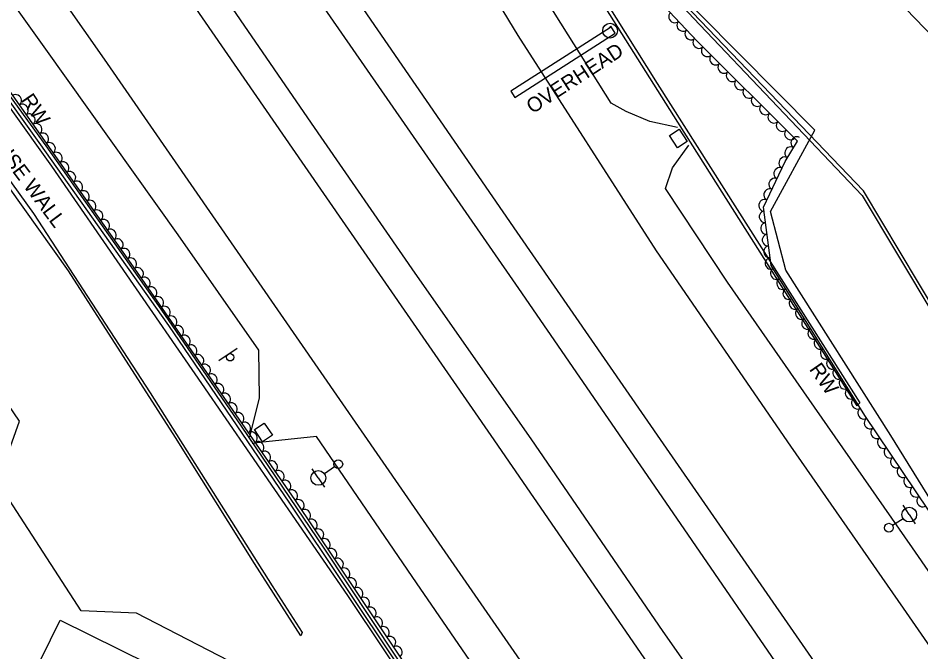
# Model space of a CAD drawing. Extents: x 1722896 to 1754269, y 648279 to 666297.
# Drawn here: x 1731749.4 to 1732056.4, y 650839.6 to 651055.3 of the extents above; entities that cross this region are included whole.
import ezdxf

# ---------------------------------------------------------------- set-up
doc = ezdxf.new("R2010")
doc.units = 0
for name, color, linetype in [('DESIGN - CENTERLINE - Proposed Text', 7, 'Continuous'), ('DESIGN - PUBLIC HEARING - Shapes', 7, 'Continuous'), ('DESIGN - SCRATCH - User 1', 7, 'Continuous'), ('SURVEY - CENTERLINE - Preliminary', 7, 'Continuous'), ('SURVEY - CENTERLINE - Preliminary Text', 7, 'Continuous'), ('SURVEY - DRAINAGE - Natural Features', 7, 'Continuous'), ('SURVEY - DTM - Breaklines', 7, 'Continuous'), ('SURVEY - VEGETATION - Features with Text', 7, 'Continuous')]:
    doc.layers.add(name, color=color, linetype=linetype)

msp = doc.modelspace()

# ---------------------------------------------------------------- linework, layer by layer
at = {"layer": 'DESIGN - CENTERLINE - Proposed Text'}
msp.add_lwpolyline([(1731780.41, 650808.63), (1731750.38, 650823.44), (1731763.68, 650850.4), (1731793.71, 650835.59)], close=True, dxfattribs=at)
at = {"layer": 'DESIGN - PUBLIC HEARING - Shapes'}
for p, q in [((1731950.78, 651052.04), (1731916.88, 651030.45)), ((1731950.91, 651052.54), (1731950.38, 651051.91)), ((1731952.44, 651050.16), (1731950.91, 651052.54)), ((1731918.25, 651028.26), (1731952.44, 651050.16)), ((1731950.68, 651050.98), (1731950.68, 651050.98)), ((1731916.88, 651030.45), (1731918.25, 651028.26)), ((1731817.67, 650938.77), (1731823.88, 650942.97))]:
    msp.add_line(p, q, dxfattribs=at)
for centre, radius in [((1731950.68, 651051), 2.5), ((1731821.48, 650939.87), 1.25)]:
    msp.add_circle(centre, radius, dxfattribs=at)
at = {"layer": 'DESIGN - SCRATCH - User 1'}
for points in [[(1731680.63, 651501.51), (1731706.68, 651458.5), (1731762.77, 651364.89), (1731797.2, 651307.65), (1731864.33, 651196.37), (1731896.93, 651142.43), (1731941.96, 651095.08), (1731979.08, 651055.22), (1732036.37, 650994.91), (1732060.81, 650954.19), (1732114.18, 650865.36), (1732129.08, 650840.67), (1732130.55, 650841.67), (1732086.72, 650912.98), (1732036.79, 650996.49), (1731973.45, 651062.76), (1731898, 651143.62), (1731862.11, 651202.73), (1731801.43, 651303.37), (1731762.87, 651367.01), (1731706.71, 651460.76), (1731681.59, 651502.39), (1731680.63, 651501.51)], [(1731845.46, 650845.06), (1731829.79, 650869.74), (1731802.93, 650912.6), (1731766.54, 650969.25), (1731721.31, 651032.63), (1731670.36, 651104.51), (1731614.93, 651181.38), (1731578.56, 651233.28), (1731531.39, 651304.53), (1731532.39, 651305.05), (1731571.46, 651245.99), (1731615.93, 651181.71), (1731665.93, 651112.54), (1731712.43, 651047.28), (1731754.65, 650988.78), (1731794.25, 650927.74), (1731835.8, 650862.08), (1731846.02, 650846.2), (1731845.46, 650845.06)], [(1732034.69, 650923.36), (1732003.06, 650973.48), (1731972.32, 651022.07), (1731941.05, 651071.73), (1731904.54, 651126.39), (1731894.7, 651142.29), (1731894.86, 651142.36)], [(1731895.88, 651142.78), (1731895.94, 651142.8), (1731906.58, 651125.2), (1731941.84, 651072.73), (1731966.69, 651032.99), (1731998.4, 650983.02), (1732035.61, 650924.43), (1732034.69, 650923.36)], [(1731711.45, 651075.97), (1731756.46, 651012.92), (1731800.47, 650950.64), (1731841.61, 650890.2), (1731878.83, 650834.58), (1731941.61, 650740.85), (1731974.68, 650690.75), (1731975.76, 650691.44), (1731953.79, 650724.47), (1731919.13, 650776.17), (1731885.86, 650826.09), (1731853.46, 650874.88), (1731825.32, 650916.45), (1731798.06, 650956.2), (1731758.89, 651011.87), (1731723.91, 651060.09)]]:
    msp.add_lwpolyline(points, dxfattribs=at)
at = {"layer": 'SURVEY - CENTERLINE - Preliminary'}
for points in [[(1731987.56, 651124.54), (1732076.69, 651031.96), (1732139.09, 650944.54), (1732141.6, 650942.26)], [(1732086.13, 650848.59), (1732046.09, 650913.21), (1732010.44, 650969.5), (1732005.18, 650989.51), (1732020.29, 651017.12), (1731968.54, 651069.55)], [(1731719.74, 651062.41), (1731760.69, 651004.94), (1731811.77, 650930.95), (1731861.34, 650858.86), (1731911.05, 650784.52), (1731953.32, 650720.36), (1731972.7, 650690.52), (1731957.5, 650673.39), (1731935.16, 650693.97), (1731925.57, 650696.42), (1731909.01, 650693.57), (1731912.5, 650678.75), (1731923.45, 650652.45), (1731950.19, 650614.84)], [(1731941.83, 650605.02), (1731903.93, 650655.14), (1731868.65, 650709.61), (1731883.74, 650722.54), (1731896.34, 650740.19), (1731872.01, 650780.24), (1731857.08, 650775.11), (1731841.22, 650782.51), (1731846.88, 650797.67), (1731841.95, 650819.95), (1731828.03, 650832.91), (1731789.69, 650852.77), (1731770.8, 650853.6), (1731742.33, 650897.36), (1731749.84, 650918.11), (1731736.25, 650937.95)]]:
    msp.add_lwpolyline(points, dxfattribs=at)
at = {"layer": 'SURVEY - CENTERLINE - Preliminary Text'}
for points in [[(1731973.59, 651018.03), (1731964.22, 651020.08), (1731956.1, 651023.54), (1731951.02, 651026.37), (1731931.96, 651056.63), (1731892.47, 651121.33), (1731857.59, 651177.14), (1731825.98, 651228.44), (1731803.59, 651264.54), (1731802.08, 651263.28), (1731780.81, 651294.54), (1731758.29, 651329.07), (1731711.05, 651401.41), (1731683.3, 651444.9), (1731661.53, 651480.68)], [(1732085.65, 650803.56), (1732050.4, 650854.57), (1732012.17, 650909.59), (1731966.42, 650976.11), (1731919.38, 651049.41), (1731882.1, 651110.79), (1731849.88, 651162.67), (1731820.44, 651210.26), (1731770.77, 651290.85), (1731726.03, 651363.67), (1731682.44, 651434.5), (1731656.79, 651476.05)], [(1731616.26, 651421.62), (1731673.55, 651338.68), (1731726.54, 651261.54), (1731771.3, 651196.63), (1731821.79, 651123.39), (1731866.78, 651058.16), (1731918.97, 650982.49), (1731968.69, 650910.45), (1732015.97, 650842.13), (1732059.47, 650779.19)], [(1731609.29, 651412.47), (1731640.1, 651367.94), (1731672.44, 651320.08), (1731705.09, 651273.95), (1731739.88, 651223.41), (1731771.76, 651177.96), (1731804.85, 651129.23), (1731841.88, 651075.46), (1731880.61, 651019.43), (1731919.55, 650963.26), (1731970.71, 650888.77), (1732015.82, 650823.2), (1732046.06, 650780.13), (1732051.86, 650771.78)], [(1732032.9, 650754.58), (1732001.01, 650800.45), (1731968.72, 650846.62), (1731923.79, 650912.09), (1731884.37, 650968.55), (1731849.18, 651019.58), (1731812.26, 651073.26), (1731756.99, 651153.56), (1731679.87, 651265.16), (1731634.52, 651331.21), (1731592.81, 651391.29)], [(1732025.14, 650747.43), (1731976.82, 650816.5), (1731910.23, 650913.3), (1731847.03, 651004.74), (1731792.34, 651084.02), (1731736.24, 651165.32), (1731675.77, 651253.11), (1731613.26, 651343.4), (1731586.88, 651382.19)], [(1731558.13, 651341.59), (1731611.18, 651270.98), (1731669.4, 651193.37), (1731730.92, 651109.38), (1731778.62, 651041.25), (1731831.25, 650965.22), (1731893.44, 650875.12), (1731953.62, 650788.12), (1731998.3, 650723.5)], [(1731828.16, 650912.84), (1731831.44, 650926.12), (1731831.28, 650942.25), (1731803.84, 650981.51), (1731758.79, 651044.68), (1731711.49, 651110.83), (1731670.01, 651168.59), (1731629.92, 651224.18), (1731584.4, 651287.39), (1731550.85, 651332.66)], [(1732095.97, 650813.6), (1732086.47, 650827.35), (1732053.52, 650875.04), (1732020.23, 650922.85), (1731990.63, 650965.39), (1731969.53, 650997.26), (1731971.88, 651004.35), (1731977.41, 651012.05)], [(1731988.06, 650713.96), (1731958.33, 650756.26), (1731921.08, 650810.29), (1731884.84, 650863.16), (1731850.81, 650912.9), (1731831.53, 650910.92), (1731828.99, 650910.56)]]:
    msp.add_lwpolyline(points, dxfattribs=at)
at = {"layer": 'SURVEY - DRAINAGE - Natural Features'}
for p, q in [((1731973.9, 651014.3), (1731973.9, 651014.3)), ((1731832.8, 650914.3), (1731832.8, 650914.3))]:
    msp.add_line(p, q, dxfattribs=at)
for points in [[(1731970.86, 651015.3), (1731974.2, 651017.49), (1731976.94, 651013.31), (1731973.6, 651011.12), (1731970.86, 651015.3)], [(1731829.75, 650915.28), (1731833.08, 650917.49), (1731835.85, 650913.32), (1731832.52, 650911.11), (1731829.75, 650915.28)]]:
    msp.add_lwpolyline(points, dxfattribs=at)
at = {"layer": 'SURVEY - DTM - Breaklines'}
for p, q in [((1731851.46, 650898.81), (1731849.32, 650901.89)), ((1731857.01, 650902.65), (1731853.52, 650900.23)), ((1731851.46, 650898.81), (1731853.6, 650895.73)), ((1732052.42, 650886.36), (1732050.39, 650889.51)), ((1732052.42, 650886.36), (1732054.46, 650883.2)), ((1732046.75, 650882.7), (1732050.32, 650885))]:
    msp.add_line(p, q, dxfattribs=at)
for centre, radius in [((1731858.24, 650903.51), 1.5), ((1731851.46, 650898.81), 2.5), ((1732052.42, 650886.36), 2.5), ((1732045.49, 650881.88), 1.5)]:
    msp.add_circle(centre, radius, dxfattribs=at)
at = {"layer": 'SURVEY - VEGETATION - Features with Text'}
for points in [[(1731530.89, 651319.05), (1731544.8, 651312.52), (1731576.63, 651263.74), (1731630.16, 651191.72), (1731685.22, 651113.78), (1731734.6, 651047.2), (1731791.48, 650966.44), (1731843.4, 650891.46), (1731899.83, 650807.18), (1731951.2, 650728.8), (1731974.6, 650694.21), (1731967.75, 650683.16), (1731959.89, 650675.49), (1731953.96, 650673.37), (1731949.61, 650676.7), (1731938.65, 650685.2), (1731929.31, 650693.1), (1731920.84, 650695.65), (1731912.41, 650691.48), (1731911.03, 650689.1), (1731921.95, 650666.12), (1731927.9, 650651.9), (1731954.2, 650614.68), (1731943.01, 650602.57)], [(1732236.41, 650804.23), (1732221.96, 650790.42), (1732206.79, 650789.89), (1732190.78, 650792.42), (1732172.9, 650795.01), (1732158.48, 650800.33), (1732149.18, 650802.17), (1732140.53, 650808.37), (1732131.57, 650816.91), (1732127.28, 650828.29), (1732118.85, 650825.83), (1732111.88, 650818.36), (1732106.8, 650818.16), (1732100, 650825.57), (1732085.7, 650844.61), (1732063.41, 650881.31), (1732037.28, 650920.08), (1732005.41, 650971.08), (1732002.86, 650990.97), (1732010.17, 651006.46), (1732014.37, 651013.43), (1731980.28, 651047.46), (1731938.47, 651091.92)]]:
    msp.add_lwpolyline(points, dxfattribs=at)
for centre, major_axis in [((1731972.58, 651055.65), (-1.37, 1.46)), ((1731975.32, 651052.74), (-1.37, 1.46)), ((1731978.06, 651049.82), (-1.37, 1.46)), ((1731980.81, 651046.93), (-1.42, 1.41)), ((1731983.65, 651044.1), (-1.42, 1.41)), ((1731986.48, 651041.28), (-1.42, 1.41)), ((1731989.31, 651038.45), (-1.42, 1.41)), ((1731992.14, 651035.62), (-1.42, 1.41)), ((1731994.97, 651032.8), (-1.42, 1.41)), ((1731997.8, 651029.97), (-1.42, 1.41)), ((1731748.61, 651027.3), (1.15, -1.64)), ((1732000.63, 651027.15), (-1.42, 1.41)), ((1731750.91, 651024.03), (1.15, -1.64)), ((1732003.46, 651024.32), (-1.42, 1.41)), ((1731753.22, 651020.76), (1.15, -1.64)), ((1732006.29, 651021.5), (-1.42, 1.41)), ((1731755.52, 651017.49), (1.15, -1.64)), ((1732009.13, 651018.67), (-1.42, 1.41)), ((1731757.82, 651014.22), (1.15, -1.64)), ((1732011.96, 651015.84), (-1.42, 1.41)), ((1732014.07, 651012.93), (1.03, 1.71)), ((1731760.13, 651010.95), (1.15, -1.64)), ((1731762.43, 651007.68), (1.15, -1.64)), ((1732012, 651009.51), (1.03, 1.71)), ((1731764.73, 651004.41), (1.15, -1.64)), ((1732009.98, 651006.06), (0.85, 1.81)), ((1731767.04, 651001.14), (1.15, -1.64)), ((1732008.27, 651002.44), (0.85, 1.81)), ((1731769.34, 650997.87), (1.15, -1.64)), ((1732006.56, 650998.82), (0.85, 1.81)), ((1731771.64, 650994.6), (1.15, -1.64)), ((1732004.86, 650995.21), (0.85, 1.81)), ((1731773.95, 650991.33), (1.15, -1.64)), ((1732003.15, 650991.59), (0.85, 1.81)), ((1731776.25, 650988.06), (1.15, -1.64)), ((1732003.28, 650987.68), (-0.25, 1.98)), ((1731778.55, 650984.79), (1.15, -1.64)), ((1732003.79, 650983.71), (-0.25, 1.98)), ((1731780.86, 650981.52), (1.15, -1.64)), ((1732004.3, 650979.75), (-0.25, 1.98)), ((1731783.16, 650978.25), (1.15, -1.64)), ((1731785.46, 650974.98), (1.15, -1.64)), ((1732004.8, 650975.78), (-0.25, 1.98)), ((1731787.77, 650971.71), (1.15, -1.64)), ((1732005.31, 650971.81), (-0.25, 1.98)), ((1731790.07, 650968.43), (1.15, -1.64)), ((1732007.14, 650968.31), (-1.06, 1.7)), ((1731792.36, 650965.16), (1.14, -1.64)), ((1732009.26, 650964.92), (-1.06, 1.7)), ((1731794.64, 650961.87), (1.14, -1.64)), ((1732011.38, 650961.53), (-1.06, 1.7)), ((1731796.92, 650958.58), (1.14, -1.64)), ((1732013.5, 650958.14), (-1.06, 1.7)), ((1731799.19, 650955.29), (1.14, -1.64)), ((1731801.47, 650952), (1.14, -1.64)), ((1732015.62, 650954.75), (-1.06, 1.7)), ((1731803.75, 650948.72), (1.14, -1.64)), ((1732017.74, 650951.35), (-1.06, 1.7)), ((1731806.03, 650945.43), (1.14, -1.64)), ((1732019.86, 650947.96), (-1.06, 1.7)), ((1731808.3, 650942.14), (1.14, -1.64)), ((1732021.98, 650944.57), (-1.06, 1.7)), ((1732024.1, 650941.18), (-1.06, 1.7)), ((1731810.58, 650938.85), (1.14, -1.64)), ((1732026.22, 650937.79), (-1.06, 1.7)), ((1731812.86, 650935.56), (1.14, -1.64)), ((1732028.34, 650934.39), (-1.06, 1.7)), ((1731815.14, 650932.27), (1.14, -1.64)), ((1732030.46, 650931), (-1.06, 1.7)), ((1731817.41, 650928.98), (1.14, -1.64)), ((1732032.58, 650927.61), (-1.06, 1.7)), ((1731819.69, 650925.7), (1.14, -1.64)), ((1732034.7, 650924.22), (-1.06, 1.7)), ((1731821.97, 650922.41), (1.14, -1.64)), ((1731824.24, 650919.12), (1.14, -1.64)), ((1732036.82, 650920.83), (-1.06, 1.7)), ((1731826.52, 650915.83), (1.14, -1.64)), ((1732039.03, 650917.49), (-1.12, 1.66)), ((1731828.8, 650912.54), (1.14, -1.64)), ((1732041.26, 650914.17), (-1.12, 1.66)), ((1731831.08, 650909.25), (1.14, -1.64)), ((1732043.5, 650910.86), (-1.12, 1.66)), ((1731833.35, 650905.97), (1.14, -1.64)), ((1732045.73, 650907.54), (-1.12, 1.66)), ((1731835.63, 650902.68), (1.14, -1.64)), ((1732047.97, 650904.22), (-1.12, 1.66)), ((1731837.91, 650899.39), (1.14, -1.64)), ((1732050.2, 650900.91), (-1.12, 1.66)), ((1731840.19, 650896.1), (1.14, -1.64)), ((1732052.44, 650897.59), (-1.12, 1.66)), ((1732054.67, 650894.27), (-1.12, 1.66)), ((1731842.46, 650892.81), (1.14, -1.64)), ((1732056.91, 650890.95), (-1.12, 1.66)), ((1731844.71, 650889.5), (1.11, -1.66)), ((1731846.94, 650886.18), (1.11, -1.66)), ((1731849.16, 650882.86), (1.11, -1.66)), ((1731851.39, 650879.53), (1.11, -1.66)), ((1731853.61, 650876.21), (1.11, -1.66)), ((1731855.84, 650872.88), (1.11, -1.66)), ((1731858.06, 650869.56), (1.11, -1.66)), ((1731860.29, 650866.24), (1.11, -1.66)), ((1731862.51, 650862.91), (1.11, -1.66)), ((1731864.74, 650859.59), (1.11, -1.66)), ((1731866.96, 650856.27), (1.11, -1.66)), ((1731869.19, 650852.94), (1.11, -1.66)), ((1731871.42, 650849.62), (1.11, -1.66)), ((1731873.64, 650846.29), (1.11, -1.66)), ((1731875.87, 650842.97), (1.11, -1.66)), ((1731878.09, 650839.65), (1.11, -1.66))]:
    msp.add_ellipse(centre, major_axis=major_axis, ratio=0.940188, start_param=0, end_param=3.141593, dxfattribs=at)

# ---------------------------------------------------------------- texts
at = {"layer": 'DESIGN - PUBLIC HEARING - Shapes'}
msp.add_text('OVERHEAD', height=5, rotation=32.9968, dxfattribs=at).set_placement((1731924.27, 651022.55))
at = {"layer": 'DESIGN - SCRATCH - User 1'}
for s, rotation, p in [('RW', 304.4449, (1731750.14, 651027.42)), ('NOISE WALL', 306.7305, (1731737.41, 651016.3)), ('RW', 304.8154, (1732018.22, 650935.78))]:
    msp.add_text(s, height=5, rotation=rotation, dxfattribs=at).set_placement(p)

doc.saveas('drawing.dxf')
